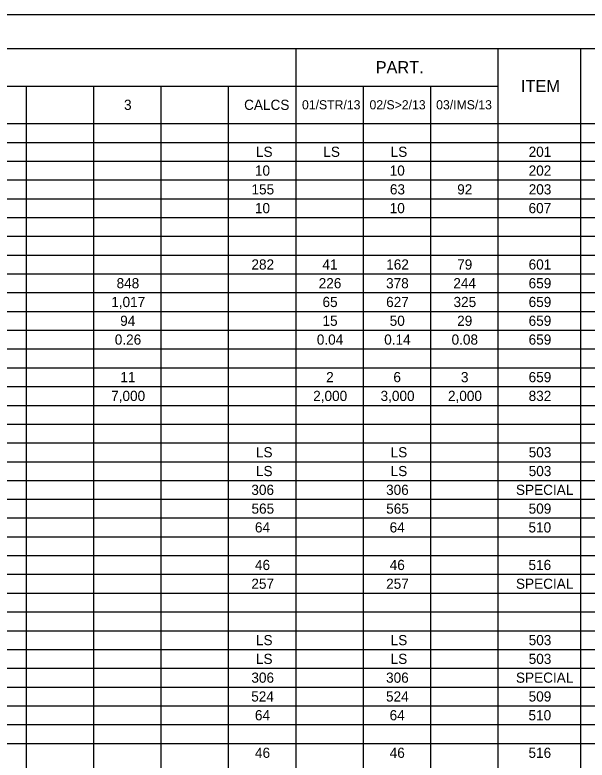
# Model space of a CAD drawing. Extents: x 0 to 34, y 0 to 22.
# Drawn here: x 8.36 to 16.9, y 10.89 to 22 of the extents above; entities that cross this region are included whole.
import ezdxf

# ---------------------------------------------------------------- set-up
doc = ezdxf.new("R2010")
doc.units = 0
for name, color, linetype in [('Default', 7, 'Continuous'), ('SH_Border', 7, 'Continuous'), ('SH_Cut_Line', 7, 'Continuous')]:
    doc.layers.add(name, color=color, linetype=linetype)

msp = doc.modelspace()

# ---------------------------------------------------------------- linework, layer by layer
at = {"layer": 'Default'}
for p, q in [((1.5, 21.5), (32.001, 21.5)), ((12.551, 21.5), (12.551, 0.502)), ((15.565, 21.5), (15.565, 0.502)), ((16.8, 21.5), (16.8, 0.502)), ((1.5, 20.94), (15.565, 20.94)), ((8.532, 20.94), (8.532, 0.502)), ((9.537, 20.94), (9.537, 0.502)), ((10.542, 20.94), (10.542, 0.502)), ((11.546, 20.94), (11.546, 0.502)), ((13.556, 20.94), (13.556, 0.502)), ((14.56, 20.94), (14.56, 0.502)), ((1.5, 20.38), (32.001, 20.38)), ((1.5, 20.1), (32.001, 20.1)), ((1.5, 19.82), (32.001, 19.82)), ((1.5, 19.54), (32.001, 19.54)), ((1.5, 19.26), (32.001, 19.26)), ((1.5, 18.98), (32.001, 18.98)), ((1.5, 18.7), (32.001, 18.7)), ((1.5, 18.42), (32.001, 18.42)), ((1.5, 18.14), (32.001, 18.14)), ((1.5, 17.86), (32.001, 17.86)), ((1.5, 17.58), (32.001, 17.58)), ((1.5, 17.3), (32.001, 17.3)), ((1.5, 17.02), (32.001, 17.02)), ((1.5, 16.74), (32.001, 16.74)), ((1.5, 16.46), (32.001, 16.46)), ((1.5, 16.18), (32.001, 16.18)), ((1.5, 15.9), (32.001, 15.9)), ((1.5, 15.62), (32.001, 15.62)), ((1.5, 15.34), (32.001, 15.34)), ((1.5, 15.061), (32.001, 15.061)), ((1.5, 14.781), (32.001, 14.781)), ((1.5, 14.501), (32.001, 14.501)), ((1.5, 14.221), (32.001, 14.221)), ((1.5, 13.941), (32.001, 13.941)), ((1.5, 13.661), (32.001, 13.661)), ((1.5, 13.381), (32.001, 13.381)), ((1.5, 13.101), (32.001, 13.101)), ((1.5, 12.821), (32.001, 12.821)), ((1.5, 12.541), (32.001, 12.541)), ((1.5, 12.261), (32.001, 12.261)), ((1.5, 11.981), (32.001, 11.981)), ((1.5, 11.701), (32.001, 11.701)), ((1.5, 11.421), (32.001, 11.421)), ((1.5, 11.141), (32.001, 11.141))]:
    msp.add_line(p, q, dxfattribs=at)
at = {"layer": 'SH_Border'}
msp.add_lwpolyline([(1.5, 21.5), (33.5, 21.5), (33.5, 0.5), (1.5, 0.5)], close=True, dxfattribs=at)
at = {"layer": 'SH_Cut_Line'}
msp.add_lwpolyline([(0, 0), (34, 0), (34, 22), (0, 22)], close=True, dxfattribs=at)

# ---------------------------------------------------------------- texts
at = {"layer": 'Default'}
for s, height, p in [('PART.', 0.1818, (13.744, 21.129)), ('ITEM', 0.1818, (15.911, 20.849)), ('3', 0.152, (9.991, 20.584)), ('CALCS', 0.1515, (11.782, 20.584)), ('01/STR/13', 0.1364, (12.645, 20.592)), ('02/S>2/13', 0.1364, (13.652, 20.592)), ('03/IMS/13', 0.1364, (14.646, 20.592)), ('LS', 0.1515, (11.958, 19.884)), ('LS', 0.1515, (12.963, 19.884)), ('LS', 0.1515, (13.967, 19.884)), ('201', 0.1515, (16.025, 19.884)), ('10', 0.1515, (11.943, 19.604)), ('10', 0.1515, (13.953, 19.604)), ('202', 0.1515, (16.025, 19.604)), ('155', 0.1515, (11.892, 19.324)), ('63', 0.1515, (13.956, 19.324)), ('92', 0.1515, (14.96, 19.324)), ('203', 0.1515, (16.026, 19.324)), ('10', 0.1515, (11.943, 19.044)), ('10', 0.1515, (13.953, 19.044)), ('607', 0.1515, (16.024, 19.044)), ('282', 0.1515, (11.891, 18.204)), ('41', 0.1515, (12.95, 18.204)), ('162', 0.1515, (13.901, 18.204)), ('79', 0.1515, (14.959, 18.204)), ('601', 0.1515, (16.025, 18.204)), ('848', 0.1515, (9.88, 17.925)), ('226', 0.1515, (12.894, 17.925)), ('378', 0.1515, (13.899, 17.925)), ('244', 0.1515, (14.902, 17.925)), ('659', 0.1515, (16.025, 17.925)), ('1,017', 0.1515, (9.8, 17.645)), ('65', 0.1515, (12.951, 17.645)), ('627', 0.1515, (13.9, 17.645)), ('325', 0.1515, (14.905, 17.645)), ('659', 0.1515, (16.025, 17.645)), ('94', 0.1515, (9.934, 17.365)), ('15', 0.1515, (12.951, 17.365)), ('50', 0.1515, (13.953, 17.365)), ('29', 0.1515, (14.959, 17.365)), ('659', 0.1515, (16.025, 17.365)), ('0.26', 0.1515, (9.853, 17.085)), ('0.04', 0.1515, (12.866, 17.085)), ('0.14', 0.1515, (13.871, 17.085)), ('0.08', 0.1515, (14.876, 17.085)), ('659', 0.1515, (16.025, 17.085)), ('11', 0.1515, (9.936, 16.525)), ('2', 0.152, (13.005, 16.525)), ('6', 0.152, (14.008, 16.525)), ('3', 0.152, (15.015, 16.525)), ('659', 0.1515, (16.025, 16.525)), ('7,000', 0.1515, (9.799, 16.245)), ('2,000', 0.1515, (12.812, 16.245)), ('3,000', 0.1515, (13.817, 16.245)), ('2,000', 0.1515, (14.822, 16.245)), ('832', 0.1515, (16.025, 16.245)), ('LS', 0.1515, (11.958, 15.405)), ('LS', 0.1515, (13.967, 15.405)), ('503', 0.1515, (16.026, 15.405)), ('LS', 0.1515, (11.958, 15.125)), ('LS', 0.1515, (13.967, 15.125)), ('503', 0.1515, (16.026, 15.125)), ('306', 0.1515, (11.89, 14.845)), ('306', 0.1515, (13.899, 14.845)), ('SPECIAL', 0.1515, (15.836, 14.845)), ('565', 0.1515, (11.892, 14.565)), ('565', 0.1515, (13.901, 14.565)), ('509', 0.1515, (16.025, 14.565)), ('64', 0.1515, (11.943, 14.285)), ('64', 0.1515, (13.952, 14.285)), ('510', 0.1515, (16.023, 14.285)), ('46', 0.1515, (11.944, 13.725)), ('46', 0.1515, (13.953, 13.725)), ('516', 0.1515, (16.023, 13.725)), ('257', 0.1515, (11.89, 13.445)), ('257', 0.1515, (13.9, 13.445)), ('SPECIAL', 0.1515, (15.836, 13.445)), ('LS', 0.1515, (11.958, 12.605)), ('LS', 0.1515, (13.967, 12.605)), ('503', 0.1515, (16.026, 12.605)), ('LS', 0.1515, (11.958, 12.325)), ('LS', 0.1515, (13.967, 12.325)), ('503', 0.1515, (16.026, 12.325)), ('306', 0.1515, (11.89, 12.045)), ('306', 0.1515, (13.899, 12.045)), ('SPECIAL', 0.1515, (15.836, 12.045)), ('524', 0.1515, (11.888, 11.765)), ('524', 0.1515, (13.898, 11.765)), ('509', 0.1515, (16.025, 11.765)), ('64', 0.1515, (11.943, 11.485)), ('64', 0.1515, (13.952, 11.485)), ('510', 0.1515, (16.023, 11.485)), ('46', 0.1515, (11.944, 10.925)), ('46', 0.1515, (13.953, 10.925)), ('516', 0.1515, (16.023, 10.925))]:
    msp.add_text(s, height=height, dxfattribs=at).set_placement(p)

doc.saveas('drawing.dxf')
